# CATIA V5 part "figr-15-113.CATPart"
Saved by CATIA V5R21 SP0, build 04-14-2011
Part number: Part1
Bounding box of the stored display mesh (mm): x -55.37 to 68.649, y -21.457 to 35.984, z 0 to 57.441
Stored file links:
  D:\CATIA V5R21 E-RESOURCES\CATIA-V5R21\catia-v5r21-prt\c15-catia-v5r20-prt\c15-catia-v5r21-figr-15-113.CATPart
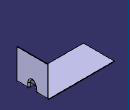
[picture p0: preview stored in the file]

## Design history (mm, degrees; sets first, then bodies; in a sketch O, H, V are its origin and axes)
SheetMetalParameters1: Thickness 1, BendRadius 2, KFactor 0.400515 {= log(min(100,max(20*SheetMetalParameters1.BendRadius,SheetMetalParameters1.Thickness)/SheetMetalParameters1.Thickness))/log(100)/2}, ReliefRadialLength 1, ReliefAxialLength 2, MinimumBendRadius 0
Body1 (main body)
  Sketch1 on xy-plane, origin (0, 0, 0), H (1, 0, 0), V (0, 1, 0)
    line L1 (-55.3695, 35.9836) -> (67.649, 35.9836)
    line L2 (67.649, 35.9836) -> (67.649, -21.4575)
    line L3 (67.649, -21.4575) -> (-55.3695, -21.4575)
    line L4 (-55.3695, -21.4575) -> (-55.3695, 35.9836)
    horizontal: L1 H, L3 H
    vertical: L2 V, L4 V
  Wall1: Thickness 1, Profile Sketch1
  d_NewWallOnEdge1: NewWallOnEdge_Edge edge [face of Wall1 | face of Wall1], NewWallOnEdge_Length 57.4411, NewWallOnEdge_HeightLimitOffset 0, NewWallOnEdge_WidthOffset1 0, NewWallOnEdge_WidthOffset2 0, NewWallOnEdge_Angle 90, NewWallOnEdge_BendRadiusValue 2 {= SheetMetalParameters1.BendRadius}, NewWallOnEdge_BendTable SheetMetalParameters1, KFacteur 0.400515 {= log(min(100,max(20*d_NewWallOnEdge1.Radius,SheetMetalParameters1.Thickness)/SheetMetalParameters1.Thickness))/log(100)/2}
  Sketch2 on , origin (67.7759, 6.9809, 0.8843), H (0.7052, 0, 0.709), V (0, -1, 0)
    point P1 (0, 0)
  d_Stamp1: Stamp_FilletRadius 2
